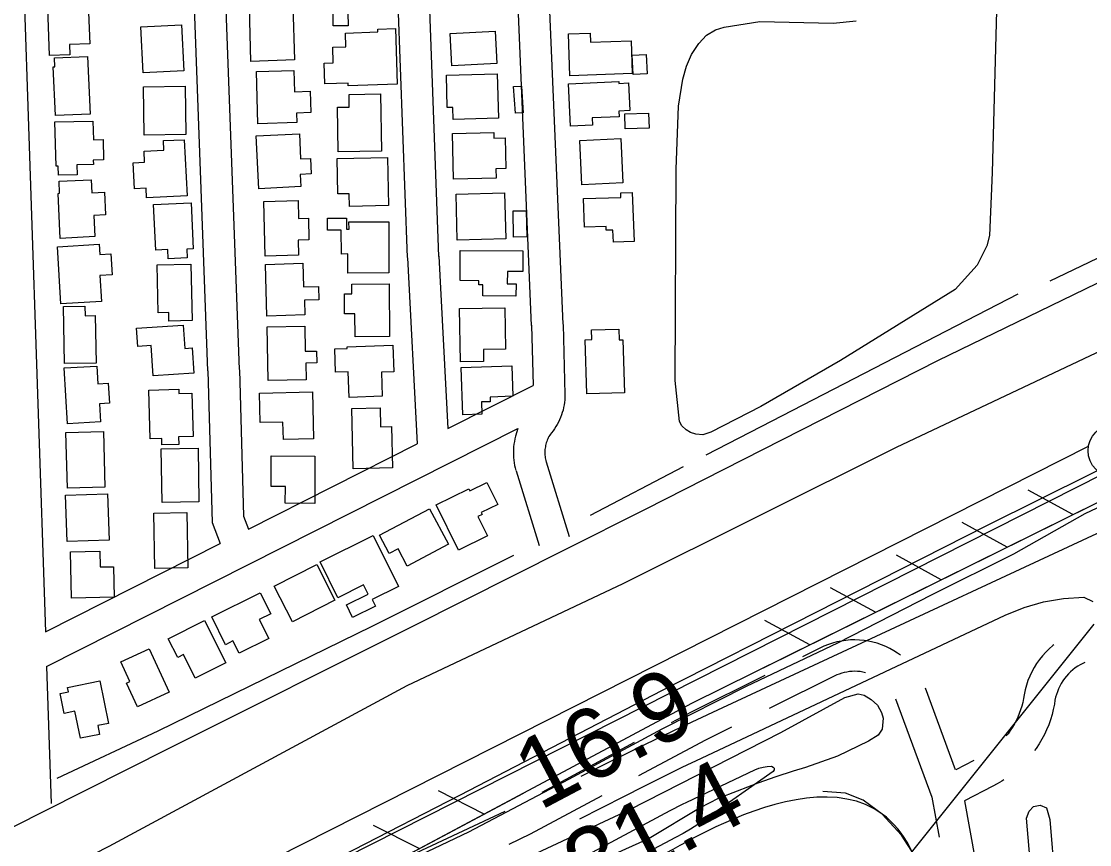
# Model space of a CAD drawing. Extents: x 3598634 to 3636690, y 517270 to 542944.
# Drawn here: x 3611508 to 3612526, y 536317 to 537102 of the extents above; entities that cross this region are included whole.
import ezdxf

# ---------------------------------------------------------------- set-up
doc = ezdxf.new("R2010")
doc.units = 0
for name, color, linetype in [('V-BLDG-OTLN', 7, 'Continuous'), ('V-BORW-LINE', 7, 'Continuous'), ('V-FLOD-BASE', 7, 'Continuous'), ('V-LEVE-TOET', 7, 'Continuous'), ('V-RIVR-RANG', 7, 'Continuous'), ('V-ROAD-CNTR', 7, 'Continuous'), ('V-RRAP-FSHR', 7, 'Continuous'), ('V-SITE-VEGE', 7, 'Continuous'), ('V-SURV-LINE', 7, 'Continuous'), ('V-TOPO-MAJR', 7, 'Continuous'), ('V-TOPO-MINR', 7, 'Continuous'), ('V-TOPO-SHOR', 7, 'Continuous')]:
    doc.layers.add(name, color=color, linetype=linetype)

msp = doc.modelspace()

# ---------------------------------------------------------------- linework, layer by layer
at = {"layer": 'V-BLDG-OTLN'}
for points in [[(3611850.4, 537110.5), (3611818.9, 537110.1), (3611819.1, 537097.9), (3611805, 537097.7), (3611804.3, 537150.8), (3611849.8, 537151.4)], [(3611571, 537125.6), (3611572.7, 537080.6), (3611553.5, 537079.9), (3611553.9, 537070.1), (3611534.4, 537069.4), (3611532.5, 537124.2)], [(3611766.5, 537116.8), (3611768.1, 537065.2), (3611726.5, 537063.9), (3611725, 537115.5)], [(3611621.5, 537096.8), (3611660.3, 537098.8), (3611662.5, 537054.8), (3611623.8, 537052.8)], [(3611816.5, 537090.9), (3611847.4, 537091.9), (3611847.3, 537094.6), (3611864.4, 537095.1), (3611866, 537042), (3611819.3, 537040.6), (3611819.2, 537043.2), (3611796.8, 537042.6), (3611796.2, 537062.1), (3611804.9, 537062.4), (3611804.5, 537077.5), (3611816.9, 537077.8)], [(3611916.4, 537090.4), (3611959.3, 537092.7), (3611960.9, 537061.8), (3611918, 537059.5)], [(3612030.5, 537050.2), (3612029.1, 537090.1), (3612050, 537090.9), (3612050.3, 537082.2), (3612088.9, 537083.6), (3612090, 537052.4)], [(3611570.7, 537068.5), (3611573, 537013.5), (3611540, 537012.1), (3611538, 537058.6), (3611539.5, 537058.7), (3611539.1, 537067.2)], [(3612103.3, 537070.5), (3612104.2, 537052), (3612090.8, 537051.4), (3612090, 537069.8)], [(3611733.1, 537004.4), (3611731.6, 537054.2), (3611767.3, 537055.3), (3611767.9, 537034.9), (3611782.9, 537035.4), (3611783.6, 537015), (3611769.8, 537014.6), (3611770.1, 537005.6)], [(3611912.8, 537050.8), (3611961.3, 537052.1), (3611962.4, 537009.6), (3611919.3, 537008.5), (3611919, 537019.9), (3611913.6, 537019.8)], [(3612029.3, 537042.5), (3612077.1, 537044.8), (3612077.2, 537042.8), (3612086.4, 537043.3), (3612087.7, 537016.9), (3612077.2, 537016.4), (3612077.5, 537011.1), (3612051.8, 537009.9), (3612052.1, 537003.1), (3612031.2, 537002.1)], [(3611663.7, 537040.3), (3611664.4, 536994.1), (3611624.8, 536993.5), (3611624, 537039.7)], [(3611978.6, 537014.4), (3611976.9, 537039.8), (3611984.4, 537040.3), (3611986.1, 537014.9)], [(3611809.6, 536977.5), (3611808.9, 537020.1), (3611820.2, 537020.3), (3611820, 537032.4), (3611850, 537033), (3611851, 536978.2)], [(3612106, 537000.1), (3612083.4, 536999.5), (3612083, 537013.9), (3612105.6, 537014.5)], [(3611540.6, 536964), (3611539.6, 537006.2), (3611575.8, 537007), (3611576.2, 536989.1), (3611585.4, 536989.3), (3611585.8, 536970), (3611576.1, 536969.7), (3611576.2, 536965.5), (3611560.6, 536965.1), (3611560.8, 536955.6), (3611543, 536955.2), (3611542.8, 536964)], [(3611733.9, 536942.3), (3611731.4, 536992.7), (3611772.6, 536994.7), (3611773.8, 536970.8), (3611783.3, 536971.3), (3611784, 536956.6), (3611773.5, 536956.1), (3611774.1, 536944.4)], [(3611960.3, 536952.4), (3611919.6, 536951.5), (3611918.6, 536995.1), (3611958.1, 536996.1), (3611958.2, 536990.7), (3611968.7, 536990.9), (3611969.4, 536961.6), (3611960.1, 536961.3)], [(3611662.9, 536989.2), (3611665.5, 536935.6), (3611626.9, 536933.7), (3611626.4, 536942.9), (3611615.5, 536942.3), (3611614.3, 536967.1), (3611625.1, 536967.6), (3611624.6, 536978.2), (3611643.4, 536979.1), (3611643, 536988.3)], [(3612042.1, 536946.1), (3612040.1, 536988.5), (3612079.1, 536990.4), (3612081.1, 536947.9)], [(3611808.7, 536971.3), (3611856.7, 536972.3), (3611857.7, 536926.4), (3611820.3, 536925.6), (3611820, 536937.7), (3611809.4, 536937.4)], [(3611544.6, 536895.1), (3611542.6, 536938), (3611544, 536938.1), (3611543.5, 536949.5), (3611574, 536951), (3611574.6, 536938.6), (3611586.8, 536939.2), (3611587.9, 536917.6), (3611576.5, 536917), (3611577.5, 536896.7)], [(3611922, 536937.2), (3611968.3, 536938.4), (3611969.5, 536894.7), (3611923.2, 536893.5)], [(3612043.5, 536933), (3612079.2, 536934.2), (3612079.1, 536938.4), (3612090.1, 536938.7), (3612091.7, 536892.2), (3612072, 536891.5), (3612071.6, 536903), (3612065.3, 536902.8), (3612065.2, 536906.3), (3612044.4, 536905.6)], [(3611633.6, 536927.3), (3611669.4, 536929), (3611671.5, 536885.1), (3611665.2, 536884.8), (3611665.6, 536876.4), (3611647.6, 536875.6), (3611647.2, 536884.4), (3611635.7, 536883.9)], [(3611740.1, 536878.2), (3611738.8, 536930.3), (3611771.5, 536931.2), (3611771.9, 536914.1), (3611781.3, 536914.4), (3611781.8, 536893.7), (3611771.4, 536893.4), (3611771.8, 536879)], [(3611857.8, 536911), (3611858, 536862.2), (3611818.9, 536862), (3611818.8, 536880.2), (3611812.7, 536880.1), (3611812.6, 536902.9), (3611799.5, 536902.8), (3611799.5, 536914.3), (3611817.6, 536914.4), (3611817.7, 536903.7), (3611820, 536903.7), (3611819.9, 536910.8)], [(3611976.9, 536896.3), (3611976.5, 536921.2), (3611989, 536921.4), (3611989.4, 536896.5)], [(3611545.1, 536832.6), (3611542, 536887.1), (3611581.7, 536889.4), (3611582.3, 536879.7), (3611592.8, 536880.3), (3611594, 536860.3), (3611582.4, 536859.7), (3611583.9, 536834.8)], [(3611925.9, 536883.5), (3611985.7, 536883.3), (3611985.6, 536863.5), (3611971, 536863.6), (3611970.9, 536851.8), (3611979.2, 536851.8), (3611979.1, 536840.1), (3611947.5, 536840.2), (3611947.5, 536850.9), (3611943.6, 536850.9), (3611943.7, 536854.7), (3611925.8, 536854.8)], [(3611741.7, 536821), (3611740.2, 536870.3), (3611775.9, 536871.4), (3611776.6, 536848.9), (3611790.9, 536849.3), (3611791.3, 536836.5), (3611777.4, 536836), (3611777.8, 536822.1)], [(3611637, 536869.8), (3611669.1, 536870.5), (3611670.3, 536816.6), (3611648.3, 536816.2), (3611648.1, 536824.3), (3611637.9, 536824.1)], [(3611858.1, 536851.7), (3611858.6, 536801.4), (3611825.7, 536801.1), (3611825.4, 536823.2), (3611815.8, 536823.1), (3611815.6, 536842.1), (3611822.6, 536842.1), (3611822.5, 536851.4)], [(3611548.8, 536775.6), (3611547.7, 536830.1), (3611568.2, 536830.5), (3611568.4, 536821.2), (3611578, 536821.4), (3611578.9, 536776.2)], [(3611925.4, 536828.1), (3611968.6, 536828.8), (3611969.2, 536789.5), (3611948.1, 536789.2), (3611948.2, 536777.6), (3611926.2, 536777.2)], [(3611672, 536766.5), (3611633.1, 536764), (3611631.3, 536792.9), (3611618.6, 536792.1), (3611617.4, 536809.5), (3611661.8, 536812.3), (3611663.3, 536790.1), (3611670.4, 536790.6)], [(3611743, 536759.4), (3611742, 536810.8), (3611777.7, 536811.5), (3611778.1, 536787.4), (3611789.1, 536787.6), (3611789.4, 536776.3), (3611778.7, 536776.1), (3611779, 536760.1)], [(3612081, 536798.3), (3612082.5, 536747.9), (3612046.6, 536746.8), (3612045, 536798.3), (3612051.4, 536798.5), (3612051.1, 536807.8), (3612077.2, 536808.6), (3612077.5, 536798.2)], [(3611818.3, 536791.7), (3611861.7, 536793.2), (3611862.6, 536767.8), (3611850.8, 536767.4), (3611851.5, 536744.5), (3611820, 536743.4), (3611819.2, 536767.8), (3611807.2, 536767.4), (3611806.4, 536789.8), (3611818.3, 536790.2)], [(3611583, 536720), (3611551.4, 536718.3), (3611548.5, 536771.5), (3611579.6, 536773.2), (3611580.5, 536756.5), (3611590.4, 536757.1), (3611591.5, 536737.9), (3611582.1, 536737.3)], [(3611927, 536771.9), (3611975.2, 536773.4), (3611976.1, 536744.5), (3611954.4, 536743.8), (3611954.5, 536739.3), (3611946.3, 536739.1), (3611946.6, 536727.5), (3611928.4, 536726.9)], [(3611630.4, 536703.9), (3611629.1, 536750.4), (3611657.6, 536751.2), (3611657.7, 536747.1), (3611670.2, 536747.5), (3611671.4, 536706.2), (3611657.4, 536705.8), (3611657.6, 536698.5), (3611641.5, 536698.1), (3611641.4, 536704.2)], [(3611734.7, 536747.4), (3611785, 536748.6), (3611786.1, 536704), (3611757.4, 536703.2), (3611756.9, 536719.9), (3611735.4, 536719.4)], [(3611861.5, 536676.2), (3611824, 536675.3), (3611822.5, 536732.9), (3611849.6, 536733.6), (3611850.1, 536715.4), (3611860.5, 536715.7)], [(3611587.2, 536657.8), (3611551.4, 536656.8), (3611550, 536710), (3611585.8, 536711)], [(3611641.7, 536643.2), (3611640.9, 536694.5), (3611676.1, 536695), (3611676.9, 536643.7)], [(3611787.3, 536642.4), (3611759.2, 536642.5), (3611759.3, 536658.3), (3611745.6, 536658.4), (3611745.7, 536687.7), (3611787.5, 536687.5)], [(3611924.5, 536597.8), (3611903.2, 536640.9), (3611934.1, 536656.2), (3611935.1, 536654.2), (3611951.5, 536662.3), (3611961.9, 536641.4), (3611946, 536633.6), (3611946.8, 536631.9), (3611942.9, 536630), (3611952.1, 536611.4)], [(3611591.3, 536607.4), (3611551.2, 536605.9), (3611549.5, 536650.1), (3611589.6, 536651.6)], [(3611875.4, 536582.6), (3611866.7, 536599.1), (3611858.2, 536594.6), (3611849, 536612), (3611896.7, 536637.3), (3611914.7, 536603.4)], [(3611665.2, 536633.6), (3611666.3, 536580.9), (3611634.8, 536580.3), (3611633.8, 536632.9)], [(3611792.3, 536586.6), (3611843.1, 536611.8), (3611867.2, 536563.2), (3611842.1, 536550.7), (3611845.3, 536544.4), (3611823.4, 536533.5), (3611817.5, 536545.5), (3611838.3, 536555.8), (3611833.9, 536564.7), (3611809.2, 536552.4)], [(3611595.3, 536582), (3611595.9, 536552.9), (3611555.4, 536552), (3611554.4, 536596.1), (3611582.5, 536596.7), (3611582.8, 536581.7)], [(3611789.2, 536584.2), (3611806.6, 536550.1), (3611766, 536529.4), (3611748.6, 536563.5)], [(3611689.1, 536534.1), (3611735.3, 536557.2), (3611745.3, 536537.1), (3611734.4, 536531.6), (3611743.5, 536513.5), (3611715.2, 536499.4), (3611709.3, 536511.2), (3611702.3, 536507.6)], [(3611682.1, 536530.7), (3611702.4, 536490.4), (3611673.3, 536475.7), (3611662, 536498.1), (3611656.6, 536495.3), (3611647.6, 536513.3)], [(3611629.3, 536503.6), (3611648.5, 536462.3), (3611618.2, 536448.2), (3611607.7, 536470.9), (3611611, 536472.4), (3611602.3, 536491.1)], [(3611582.3, 536473), (3611590.5, 536432.4), (3611580.5, 536430.4), (3611582.2, 536422), (3611563.8, 536418.3), (3611558.6, 536444.1), (3611548.5, 536442), (3611544.7, 536461.1), (3611552.5, 536462.7), (3611551.6, 536466.9)]]:
    msp.add_lwpolyline(points, close=True, dxfattribs=at)
at = {"layer": 'V-BORW-LINE'}
msp.add_lwpolyline([(3612354.1, 536238.4), (3612359.7, 536250.5), (3612365.4, 536275), (3612364.2, 536292.8), (3612359.5, 536306.1), (3612346.9, 536326.1), (3612328.4, 536346.1), (3612310.2, 536359.4), (3612293.5, 536366), (3612271.9, 536367.6)], dxfattribs=at)
msp.add_spline([(3610769.5, 535662.1), (3610801.9, 535678.9), (3610901.5, 535713), (3611018.8, 535769.3), (3611194.7, 535865.4), (3611392.7, 535942.4), (3611561.6, 536026.1), (3611723.4, 536113), (3611892.6, 536209.7), (3612070.5, 536280.6), (3612177.1, 536337.2), (3612328.4, 536346.1), (3612365.4, 536275), (3612320.4, 536188.1), (3612159.8, 536071.6), (3611939.4, 535953), (3611770.7, 535869), (3611577.6, 535780.6), (3611364.8, 535656.8), (3611233.7, 535597.2), (3611081.6, 535526.9), (3610940.9, 535453.2), (3610813.9, 535457.8), (3610782.5, 535521.1), (3610736.2, 535599.6), (3610769.5, 535662.1)], degree=3, dxfattribs=at)
at = {"layer": 'V-FLOD-BASE'}
msp.add_lwpolyline([(3613126.9, 536947.9), (3613005.9, 536895.7), (3612842.7, 536822.6), (3612628.6, 536720.8), (3612427.8, 536620.8), (3612265.2, 536538.4), (3612118.7, 536463.8), (3611925.3, 536363.9), (3611722.6, 536259.5), (3611477.8, 536138), (3611254.6, 536025.1), (3611111.1, 535951.8), (3610925.9, 535858.6), (3610829.1, 535812.2)], dxfattribs=at)
at = {"layer": 'V-LEVE-TOET'}
for points in [[(3613678.7, 537323.7), (3613393.9, 537188.7), (3613238.5, 537113.5), (3613220.5, 537105.5), (3613196.7, 537095), (3613084.3, 537034.7), (3612874.5, 536938.8), (3612572.5, 536804.8), (3612341.7, 536695.8), (3612081.2, 536565.6), (3611875, 536468.3), (3611591.1, 536315.1), (3611373.7, 536204.3), (3611078.2, 536045.7), (3610830.8, 535920.2)], [(3610826.5, 535782), (3610993.9, 535860.2), (3611088, 535906.3), (3611164.5, 535945.4), (3611248.8, 535988.2), (3611356.8, 536042), (3611457, 536088.7), (3611536.6, 536127.3), (3611632.7, 536173.4), (3611724.3, 536222.4), (3611836, 536282.4), (3611934.2, 536329.1), (3612029.6, 536379.5), (3612118.6, 536427.4), (3612198.9, 536468.1), (3612286.1, 536509.3), (3612375.9, 536555.4), (3612453.9, 536594.2), (3612521.9, 536632.8), (3612612.7, 536675.6)]]:
    msp.add_lwpolyline(points, dxfattribs=at)
at = {"layer": 'V-ROAD-CNTR'}
for p, q in [((3612398.3, 536388.2), (3612369.7, 536466.1)), ((3612375.9, 536362), (3612341.5, 536455.8)), ((3612091.9, 536414.2), (3612003.9, 536366.8))]:
    msp.add_line(p, q, dxfattribs=at)
for points in [[(3611994, 536811.9), (3611954.7, 537757.4)], [(3611905.7, 536877.9), (3611874.4, 537732)], [(3611875.8, 536876.8), (3611844.7, 537722.6)], [(3611715.4, 536769.9), (3611682.3, 537671.3)], [(3611685.4, 536768.8), (3611652.6, 537661.9)], [(3613504.4, 537298.2), (3613263.1, 537189.7), (3613226.2, 537173.1), (3612904, 537025.3), (3612651.7, 536909.6), (3612381.2, 536778.2), (3612102.9, 536636.7), (3612024.4, 536597.3), (3611881, 536525.3), (3611648.7, 536408.9), (3611528.5, 536348.3), (3611374.7, 536270.8), (3611116.8, 536138.9), (3611045.6, 536103.1), (3610844.5, 536002)], [(3611508.5, 537172.5), (3611530.5, 536519.9)], [(3612024, 536813.2), (3612011.6, 537111.6)], [(3611875.8, 536876.6), (3611884.8, 536699)], [(3611905.7, 536878.1), (3611914.1, 536713.8)], [(3611994, 536812.2), (3611995.4, 536754.9)], [(3612024, 536812.9), (3612025.7, 536746.2)], [(3611715.4, 536769.7), (3611719.3, 536630.1), (3611724.1, 536617.8)], [(3611685.4, 536768.9), (3611689.5, 536624.1), (3611697.2, 536604.1)], [(3611914.1, 536713.8), (3611995.4, 536754.9)], [(3612025.7, 536745.8), (3612025.7, 536743.6), (3612025.6, 536741.2), (3612025.3, 536738.7), (3612025, 536736.3), (3612024.5, 536733.8), (3612024, 536731.4), (3612023.3, 536729), (3612022.6, 536726.7), (3612021.7, 536724.4), (3612020.7, 536722.1), (3612019.7, 536719.9), (3612018.5, 536717.7), (3612017.3, 536715.6), (3612015.9, 536713.5), (3612014.5, 536711.5), (3612013, 536709.7), (3612012, 536708.5)], [(3611531.6, 536486.8), (3611980.8, 536713.9)], [(3611980.8, 536713.9), (3611978.7, 536706.4), (3611978.1, 536703.9), (3611977.6, 536701.4), (3611977.2, 536698.9), (3611976.9, 536696.4), (3611976.8, 536693.8), (3611976.7, 536691.3), (3611976.7, 536688.7), (3611976.9, 536686.2), (3611977.1, 536683.6), (3611977.5, 536681.1), (3611977.9, 536678.6), (3611978.5, 536676.1), (3611979.1, 536673.8), (3611979.1, 536673.6)], [(3612012.9, 536709.7), (3612012, 536708.4), (3612011.3, 536707.3), (3612010.6, 536706.1), (3612010, 536705), (3612009.5, 536703.8), (3612009, 536702.6), (3612008.5, 536701.4), (3612008.1, 536700.1), (3612007.7, 536698.8), (3612007.4, 536697.6), (3612007.2, 536696.3), (3612007, 536695), (3612006.8, 536693.7), (3612006.7, 536692.4), (3612006.7, 536691), (3612006.7, 536689.7), (3612006.8, 536688.4), (3612006.9, 536687.1), (3612007.1, 536685.8), (3612007.3, 536684.5), (3612007.6, 536683.2), (3612008, 536681.8), (3612008, 536681.8)], [(3611724.1, 536617.8), (3611884.8, 536699)], [(3612007.9, 536682.1), (3612029.9, 536610.9)], [(3611979.2, 536673.3), (3612001.3, 536602.1)], [(3611530.5, 536519.9), (3611697.2, 536604.1)], [(3612345.9, 536497.5), (3612343, 536499.6), (3612339.4, 536501.9), (3612335.6, 536504), (3612331.7, 536505.9), (3612327.7, 536507.5), (3612323.6, 536508.9), (3612319.4, 536510.1), (3612315.2, 536511), (3612311, 536511.7), (3612306.7, 536512), (3612302.4, 536512.2), (3612298, 536512.1), (3612293.7, 536511.7), (3612289.5, 536511.1), (3612285.2, 536510.2), (3612281.1, 536509.1), (3612277, 536507.8), (3612272.8, 536506.1), (3612252.3, 536495.9)], [(3612492.1, 536507.6), (3612491.1, 536506.8), (3612487.6, 536503.7), (3612484.3, 536500.5), (3612481.2, 536497), (3612478.3, 536493.4), (3612475.6, 536489.7), (3612473.2, 536485.8), (3612471, 536481.7), (3612469, 536477.5), (3612467.3, 536473.3), (3612465.8, 536468.9), (3612464.6, 536464.4), (3612463.6, 536459.9), (3612463, 536456.2), (3612462.3, 536452.6), (3612461.4, 536449), (3612460.3, 536445.5), (3612459.1, 536442), (3612457.7, 536438.6), (3612456.1, 536435.2), (3612454.4, 536432), (3612452.5, 536428.8), (3612450.5, 536425.7), (3612448.3, 536422.7), (3612446.7, 536420.6)], [(3611531.6, 536486.8), (3611536, 536356.3)], [(3612521.5, 536490.6), (3612519.8, 536489.8), (3612517.2, 536488.5), (3612514.8, 536487), (3612512.4, 536485.4), (3612510.2, 536483.6), (3612508, 536481.7), (3612506, 536479.7), (3612504, 536477.6), (3612502.3, 536475.4), (3612500.6, 536473), (3612499.1, 536470.6), (3612497.7, 536468.1), (3612496.5, 536465.5), (3612495.4, 536462.8), (3612494.5, 536460.1), (3612493.7, 536457.4), (3612493.1, 536454.6), (3612492.6, 536450.9), (3612491.5, 536445.9), (3612490.3, 536440.9), (3612488.8, 536436), (3612487.1, 536431.2), (3612485.1, 536426.5), (3612483, 536421.9), (3612480.6, 536417.4), (3612478.1, 536413), (3612475.3, 536408.7), (3612473.7, 536406.6)], [(3612216.4, 536478.2), (3612146.1, 536443.3), (3612127.2, 536433.2)], [(3612312.4, 536480.9), (3612312.3, 536480.9), (3612309.8, 536481.5), (3612307.3, 536481.9), (3612304.8, 536482.1), (3612302.2, 536482.2), (3612299.7, 536482.1), (3612297.2, 536481.9), (3612294.6, 536481.5), (3612292.1, 536481), (3612289.7, 536480.4), (3612287.3, 536479.6), (3612285.1, 536478.7), (3612220.5, 536446.7)], [(3612184.6, 536428.9), (3612159.8, 536416.7), (3612096.1, 536382.4)], [(3612415.8, 536397.1), (3612398.4, 536388.3)], [(3612444.4, 536378.7), (3612442.3, 536377.4), (3612437.9, 536374.8), (3612433.7, 536372.6), (3612406.8, 536358.8), (3612417, 536302.4)], [(3612060.9, 536363.4), (3611992.8, 536326.8), (3611972.3, 536317.2)], [(3612375.7, 536362.3), (3612382.6, 536324)], [(3611968.4, 536348.5), (3611883.7, 536308.7), (3611877.9, 536305.8)]]:
    msp.add_lwpolyline(points, dxfattribs=at)
at = {"layer": 'V-RRAP-FSHR'}
for p, q in [((3612510.2, 536631.7), (3612467.4, 536655.1)), ((3612447.5, 536600.6), (3612404.6, 536624)), ((3612384.7, 536569.5), (3612341.9, 536592.9)), ((3612322, 536538.5), (3612279.2, 536561.9)), ((3612259.3, 536507.4), (3612216.4, 536530.8)), ((3611948.7, 536346.1), (3611905.2, 536368.2)), ((3611887, 536313.1), (3611843.4, 536335.2))]:
    msp.add_line(p, q, dxfattribs=at)
for points in [[(3610283.7, 535468.8), (3610304.8, 535469.2), (3610403.3, 535553.5), (3610452.1, 535596.1), (3610565, 535662.3), (3611212.8, 535980.7), (3611755.6, 536243), (3612146.8, 536451.7), (3612655.7, 536703.7), (3613040.1, 536882.2), (3613115.5, 536910.7), (3613121.1, 536940)], [(3612215.1, 536485.5), (3612655.7, 536703.7), (3613037.8, 536881.2)], [(3610283.7, 535468.8), (3610304.8, 535469.2), (3610403.3, 535553.5), (3610452.1, 535596.1), (3610565, 535662.3), (3611212.8, 535980.7), (3611755.6, 536243), (3611986.4, 536366.1)]]:
    msp.add_lwpolyline(points, dxfattribs=at)
at = {"layer": 'V-SITE-VEGE'}
for points in [[(3612437.6, 537124.6), (3612433.1, 536957.9), (3612430.6, 536897.7), (3612428.1, 536888), (3612418.9, 536869.4), (3612397.9, 536846.4), (3612288.6, 536778.6), (3612212.5, 536734.8), (3612164.9, 536710.4), (3612157.4, 536707.8), (3612150.5, 536708.5), (3612145.6, 536710), (3612141.5, 536712.6), (3612137.3, 536716.4), (3612135, 536720.5), (3612131, 536759.5), (3612132, 536961.2), (3612134, 537021.3), (3612138.2, 537046.8), (3612141.8, 537059.4), (3612146.6, 537070.5), (3612153.5, 537080.8), (3612160.9, 537088.8), (3612169.3, 537094), (3612177.8, 537096.6), (3612211.7, 537101.9), (3612281.6, 537100.2), (3612303.6, 537102.6)], [(3611722.3, 536179.3), (3612087.6, 536350.4), (3612231.6, 536424), (3612292.7, 536457.2), (3612305.3, 536460.6), (3612311.2, 536459.4), (3612317.9, 536455.3), (3612323.9, 536449.9), (3612327.7, 536443), (3612329.3, 536437.4), (3612328.3, 536427.1), (3612324.5, 536421.4), (3612315.3, 536415.7), (3612285.6, 536401.2), (3612255.3, 536390.5), (3612243.6, 536386.9), (3612226.9, 536381.6), (3612209.7, 536375.6), (3612190.2, 536367.8), (3612171.8, 536360.8), (3612154.9, 536352), (3612106, 536322.7), (3611998.9, 536274.4)], [(3612470, 536294.1), (3612465.9, 536342.2), (3612468.4, 536348.9), (3612472.7, 536353.3), (3612479.1, 536354.6), (3612485, 536352), (3612488.2, 536340.8), (3612492.8, 536283.2)]]:
    msp.add_lwpolyline(points, dxfattribs=at)
at = {"layer": 'V-SURV-LINE'}
for points in [[(3610459.5, 535651.3), (3612525, 536696.9)], [(3612538.6, 536670.2), (3610473, 535624.6)]]:
    msp.add_lwpolyline(points, dxfattribs=at)
msp.add_circle((3612549.6, 536692.6), 25, dxfattribs=at)
at = {"layer": 'V-TOPO-MAJR'}
for points in [[(3612040.2, 536341.4), (3612082.5, 536363.2), (3612100.7, 536372.5), (3612119.1, 536381.7), (3612137.5, 536390.7), (3612156, 536399.5), (3612445.7, 536535.9), (3612463.8, 536543), (3612482.3, 536548.5), (3612501.3, 536551.5), (3612520.7, 536552.8), (3612529.3, 536548.8)], [(3612530.2, 536527.3), (3612252.9, 536180.7)]]:
    msp.add_lwpolyline(points, dxfattribs=at)
at = {"layer": 'V-TOPO-MINR'}
for points in [[(3612041.4, 536382.2), (3612068.3, 536395.8), (3612102.6, 536412.7), (3612137, 536429.3), (3612171.6, 536445.6), (3612643, 536664.7)], [(3612225.4, 536389.7), (3612225.2, 536388.3), (3612224.3, 536386.6), (3612159.3, 536340.8), (3612152.5, 536336.1), (3612145.6, 536331.7), (3612138.5, 536327.6), (3612131.3, 536323.6), (3612038.3, 536274.6)], [(3612039.1, 536302.7), (3612126.2, 536349.4), (3612130.1, 536351.5), (3612134, 536353.5), (3612138, 536355.5), (3612142, 536357.4), (3612206.9, 536388.3), (3612210.8, 536389.7), (3612214.7, 536390.9), (3612218.7, 536391.4), (3612222.8, 536391.6), (3612224.4, 536390.8), (3612225.4, 536389.7)]]:
    msp.add_lwpolyline(points, dxfattribs=at)
at = {"layer": 'V-TOPO-SHOR'}
msp.add_line((3612138.5, 536677.2), (3612049.8, 536630.8), dxfattribs=at)
for points in [[(3612889.7, 537045.7), (3612608.4, 536911.7), (3612488.3, 536854.4)], [(3612457.6, 536841.8), (3612223.1, 536720.6), (3612160.3, 536688.4)], [(3611976.7, 536592.6), (3611841.6, 536524.8), (3611637.8, 536425.1), (3611541.4, 536380.1)]]:
    msp.add_lwpolyline(points, dxfattribs=at)

# ---------------------------------------------------------------- texts
at = {"layer": 'V-RIVR-RANG'}
for s, p in [('16.9', (3612001.7, 536348.9)), ('31.4', (3612048.8, 536260.8))]:
    msp.add_text(s, height=67, rotation=27.8383, dxfattribs=at).set_placement(p)

doc.saveas('drawing.dxf')
